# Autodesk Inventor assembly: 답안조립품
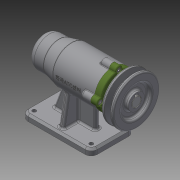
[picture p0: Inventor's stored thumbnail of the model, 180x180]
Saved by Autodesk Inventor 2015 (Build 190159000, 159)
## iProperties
Created: 2019-07
Part Number: 답안조립품
Document SubType Name: Assembly
Designer: cad-11
Author: cad-11
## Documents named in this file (12)
- C:\Users\cad-11\Desktop\이성규 490704V1043\490704V1043\답안조립품.iam
- C:\Users\cad-11\Desktop\이성규 490704V1043\490704V1043\V벨트풀리.ipt
- C:\Users\cad-11\Desktop\이성규 490704V1043\490704V1043\멈춤나사 M3.ipt
- C:\Users\cad-11\Desktop\이성규 490704V1043\490704V1043\베어링 6004.ipt
- C:\Users\cad-11\Desktop\이성규 490704V1043\490704V1043\베어링 51202.ipt
- C:\Users\cad-11\Desktop\이성규 490704V1043\490704V1043\본체.ipt
- C:\Users\cad-11\Desktop\이성규 490704V1043\490704V1043\볼트 M4.ipt
- C:\Users\cad-11\Desktop\이성규 490704V1043\490704V1043\어댑터슬리브.ipt
- C:\Users\cad-11\Desktop\이성규 490704V1043\490704V1043\오일 실.ipt
- C:\Users\cad-11\Desktop\이성규 490704V1043\490704V1043\축.ipt
- C:\Users\cad-11\Desktop\이성규 490704V1043\490704V1043\커버.ipt
- C:\Users\cad-11\Desktop\이성규 490704V1043\490704V1043\키 5 x 5 x 16.ipt
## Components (1 placed, 1 different names)
1. V벨트풀리:1
